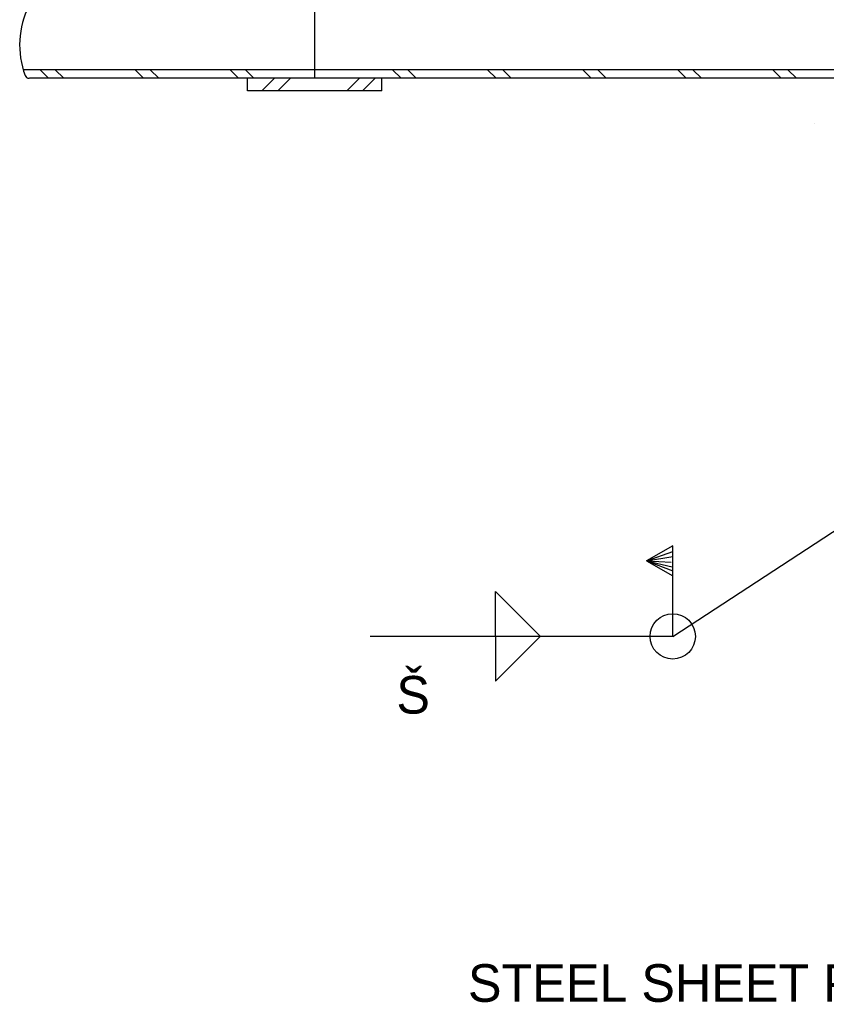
# Model space of a CAD drawing. Extents: x 22339.2 to 22413.4, y 22369.6 to 22418.8.
# Drawn here: x 22339.239 to 22343.24, y 22391.783 to 22396.66 of the extents above; entities that cross this region are included whole.
import ezdxf

# ---------------------------------------------------------------- set-up
doc = ezdxf.new("R2010")
doc.units = 0
for name, color, linetype in [('Level 1', 7, 'Continuous'), ('Level 10', 7, 'Continuous'), ('Level 2', 7, 'Continuous'), ('Level 4', 7, 'Continuous'), ('Level 8', 7, 'Continuous')]:
    doc.layers.add(name, color=color, linetype=linetype)

msp = doc.modelspace()

# ---------------------------------------------------------------- linework, layer by layer
at = {"layer": 'Level 1'}
msp.add_line((22343.1834, 22396.1426), (22343.1834, 22396.1426), dxfattribs=at)
for centre, radius, start, end in [((22339.6744, 22396.5336), 0.4356, 153.3929, 200.1919), ((22339.2856, 22396.3906), 0.0213, 200.3155, 270)]:
    msp.add_arc(centre, radius, start, end, dxfattribs=at)
at = {"layer": 'Level 10'}
for p, q in [((22342.4783, 22393.5993), (22345.4524, 22395.5406)), ((22342.4783, 22394.0493), (22342.3481, 22393.9743)), ((22342.3481, 22393.9743), (22342.4783, 22394.0212)), ((22342.4783, 22393.5993), (22342.4783, 22394.0493)), ((22342.3481, 22393.9743), (22342.4783, 22393.9957)), ((22342.3481, 22393.9743), (22342.478, 22393.8993)), ((22342.3481, 22393.9743), (22342.4711, 22393.9678)), ((22342.3481, 22393.9743), (22342.4756, 22393.9447)), ((22342.3481, 22393.9743), (22342.4783, 22393.9237)), ((22341.5996, 22393.822), (22341.8231, 22393.5985)), ((22341.5996, 22393.597), (22341.5996, 22393.822)), ((22342.4783, 22393.5993), (22340.9778, 22393.5993)), ((22341.5996, 22393.6017), (22341.5996, 22393.3767)), ((22341.5996, 22393.3767), (22341.8231, 22393.6002))]:
    msp.add_line(p, q, dxfattribs=at)
msp.add_circle((22342.4783, 22393.5993), 0.1125, dxfattribs=at)
at = {"layer": 'Level 2'}
for p, q in [((22340.7024, 22396.3688), (22340.7024, 22397.0875)), ((22345.9524, 22396.4104), (22339.2566, 22396.4104)), ((22345.9524, 22396.3688), (22339.2869, 22396.3688)), ((22340.3691, 22396.3063), (22340.3691, 22396.3688)), ((22341.0357, 22396.3063), (22341.0357, 22396.3688)), ((22341.0357, 22396.3063), (22340.3691, 22396.3063))]:
    msp.add_line(p, q, dxfattribs=at)
at = {"layer": 'Level 8'}
for points in [[(22339.3817, 22396.3688), (22339.34, 22396.4104)], [(22339.4571, 22396.3688), (22339.4155, 22396.4104)], [(22339.8531, 22396.3688), (22339.8114, 22396.4104)], [(22339.9285, 22396.3688), (22339.8869, 22396.4104)], [(22340.3245, 22396.3688), (22340.2829, 22396.4104)], [(22340.3999, 22396.3688), (22340.3583, 22396.4104)], [(22341.1306, 22396.3688), (22341.0889, 22396.4104)], [(22341.206, 22396.3688), (22341.1643, 22396.4104)], [(22341.602, 22396.3688), (22341.5603, 22396.4104)], [(22341.6774, 22396.3688), (22341.6357, 22396.4104)], [(22342.0734, 22396.3688), (22342.0317, 22396.4104)], [(22342.1488, 22396.3688), (22342.1071, 22396.4104)], [(22342.5448, 22396.3688), (22342.5031, 22396.4104)], [(22342.6202, 22396.3688), (22342.5785, 22396.4104)], [(22343.0162, 22396.3688), (22342.9745, 22396.4104)], [(22343.0916, 22396.3688), (22343.05, 22396.4104)], [(22340.5024, 22396.3688), (22340.4399, 22396.3063)], [(22340.5821, 22396.3688), (22340.5196, 22396.3063)], [(22340.9243, 22396.3688), (22340.8618, 22396.3063)], [(22341.0019, 22396.3688), (22340.9394, 22396.3063)]]:
    msp.add_lwpolyline(points, dxfattribs=at)

# ---------------------------------------------------------------- texts
at = {"layer": 'Level 4'}
for s, height, p in [('Š', 0.1867, (22341.1075, 22393.2159)), ('STEEL SHEET PILING', 0.186667, (22341.4626, 22391.7856))]:
    msp.add_text(s, height=height, dxfattribs=at).set_placement(p)

doc.saveas('drawing.dxf')
